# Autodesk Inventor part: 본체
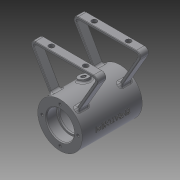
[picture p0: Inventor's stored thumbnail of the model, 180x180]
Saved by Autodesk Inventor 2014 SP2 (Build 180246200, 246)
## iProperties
Created: 2016-03
Part Number: 본체
Material: Generic
Document SubType Name: Modeling
Designer: 703
Density: 1 g/cm^3
Appearance: Default
Author: 703
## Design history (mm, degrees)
sketch "스케치1"
  geometry: 1 further point
sketch "스케치2"
  geometry: C1 r 26 at (0, 0); 1 further point
  constraints: 1 centre point
  dimensions: "d0" = 52 diameter of C1
extrude "돌출1" new body sketch "스케치2" stored distance "d1" = 70; taper "d2" = 0 deg
sketch "스케치3"
  geometry: C1 r 16 at (0, 0)
  constraints: 1 centre point
  dimensions: "d3" = 32 diameter of C1
extrude "돌출2" cut sketch "스케치3" distance "d4" = 12; taper "d5" = 0 deg
sketch "스케치4"
  geometry: C1 r 21 at (0, 0); 1 further point
  constraints: 1 centre point
  dimensions: "d6" = 42 diameter of C1
extrude "돌출3" cut sketch "스케치4" stored distance "d7" = 42; taper "d8" = 0 deg
sketch "스케치5"
  geometry: C1 r 14 at (0, 0)
  constraints: 1 centre point
  dimensions: "d9" = 28 diameter of C1
extrude "돌출4" cut sketch "스케치5" distance "d10" = 10; taper "d11" = 0 deg
sketch "스케치6"
  geometry: C1 r 16 at (0, 0)
  constraints: 1 centre point
  dimensions: "d12" = 32 diameter of C1
extrude "돌출5" cut sketch "스케치6" distance "d13" = 12; taper "d14" = 0 deg
sketch "스케치7"
  geometry: C1 r 14 at (0, 0)
  constraints: 1 centre point
  dimensions: "d15" = 28 diameter of C1
extrude "돌출6" cut sketch "스케치7" distance "d16" = 12; taper "d17" = 0 deg
sketch "스케치8"
  geometry: C1 r 21 at (0, 0); 4 further points
  constraints: 1 centre point
  dimensions: "d18" = 42 diameter of C1
hole "구멍1" sketch "스케치8" at (0, 20.989), (20.973, 0), (0, -21), (-20.998, 0) diameter "d19" = 3.242; stored, may be unused: countersink angle "d23" = 90 deg, drill point angle "d25" = 118 deg; dims "d20" = 8, "d21" = 4, "d22" = 2, "d24" = 10
node "작업 평면2"
  node "작업 평면1"
sketch "스케치9"
  geometry: C1 r 5 at (0, 0); 1 further point
  constraints: 1 centre point
  dimensions: "d27" = 10 diameter of C1
extrude "돌출7" join sketch "스케치9" stored distance "d28" = 12; taper "d29" = 0 deg
node "작업 평면4"
sketch "스케치14"
  geometry: L1 (42.594, 65)-(-42.594, 65); L2 (-15.407, 17.911)-(-42.594, 65); L3 (-16.613, 20)-(45.415, 20); L4 (15.407, 17.911)-(42.594, 65); L5 (12.994, 19.732)-(37.398, 62); L6 (37.398, 62)-(0, 62); L7 (-12.994, 19.732)-(-37.398, 62); L8 (-37.398, 62)-(0, 62); C1 r 26 at (0, 0) reference; C2 r 26 at (0, 0); A1 r 23.626 centre (0, 0) between (15.407, 17.911) and (12.577, 20); A2 r 23.626 centre (0, 0) between (-12.577, 20) and (-15.407, 17.911); 2 further points
  constraints: 16 end point, 6 point on circle, 3 centre point, 3 point on line, 1 horizontal, 1 midpoint, 1 vertical alignment
  dimensions: "d51" = 65 distance from line of point (0, 0) L1; "d54" = 120 deg angle of L3 L2; "d55" = 3 distance between parallel lines of L4 L5; "d56" = 3 distance between parallel lines of L1 L6
extrude "돌출9" join sketch "스케치14" distance "d57" = 10; taper "d58" = 0 deg
sketch "스케치15"
  geometry: L1 (0, 0)-(85.188, 0) reference; L2 (93.836, 5)-(-8.648, 5); L3 (42.594, 5)-(42.594, 13.621); L4 (62.594, 21.917)-(62.594, -11.131); C1 r 3 at (62.594, 5); C2 r 3 at (22.594, 5); 2 further points
  constraints: 6 end point, 2 centre point, 1 midpoint, 1 symmetric about line, 1 vertical alignment, 1 other
  dimensions: "d59" = 5 distance between parallel lines of L1 L2; "d60" = 20 distance between parallel lines of L3 L4; "d61" = 6 diameter of C1
extrude "돌출10" cut sketch "스케치15" distance "d62" = 10; taper "d63" = 0 deg
node "작업 평면5"
sketch "스케치16"
  geometry: L1 (19.102, -7.182)-(-18.331, -7.182); L2 (-18.331, -7.182)-(-18.331, 7.6); L3 (-18.331, 7.6)-(19.102, 7.6); L4 (19.102, 7.6)-(19.102, -7.182); 1 further point
  constraints: 2 other
feature "엠보싱1" sketch "스케치16" dims "d64" = 0.5, "d65" = 0
sketch "스케치17"
  geometry: L1 (0, 0)-(7.506, 28.012); L2 (0, 0)-(29, 0); 1 further point
  constraints: 4 end point, 1 equal length, 1 horizontal
  dimensions: "d66" = 29 distance of L1.start L1.end; "d67" = 75 deg angle of L2 L1
node "작업 평면6"
sketch "스케치18"
  geometry: C1 r 6 at (0, 0); 1 further point
  constraints: 1 centre point
  dimensions: "d68" = 12 diameter of C1
extrude "돌출11" join sketch "스케치18" stored distance "d69" = 10; taper "d70" = 0 deg
sketch "스케치19"
  geometry: 1 further point
hole "구멍4" sketch "스케치19" at (0, 0) diameter "d71" = 5.188; stored, may be unused: countersink angle "d75" = 90 deg, drill point angle "d77" = 118 deg; dims "d72" = 15, "d73" = 4, "d74" = 2, "d76" = 15
sketch "스케치20"
  geometry: 1 further point
hole "구멍5" sketch "스케치20" at (0, 0) diameter "d78" = 5.188; stored, may be unused: countersink angle "d82" = 90 deg, drill point angle "d84" = 118 deg; dims "d79" = 15, "d80" = 4, "d81" = 2, "d83" = 15
fillet "모깎기5" dims "d97" = 5, "d98" = 2, "d99" = 2, "d100" = 0.3, "d106" = 3
fillet "모깎기6" dims "d101" = 3, "d102" = 0.5
chamfer "모따기2" distance "d103" = 1; stored, may be unused: second distance "d104" = 2, angle "d105" = 45 deg
node "솔리드1"
mirror "대칭1"
mirror "대칭2"
other parameters: "d26" = -3
